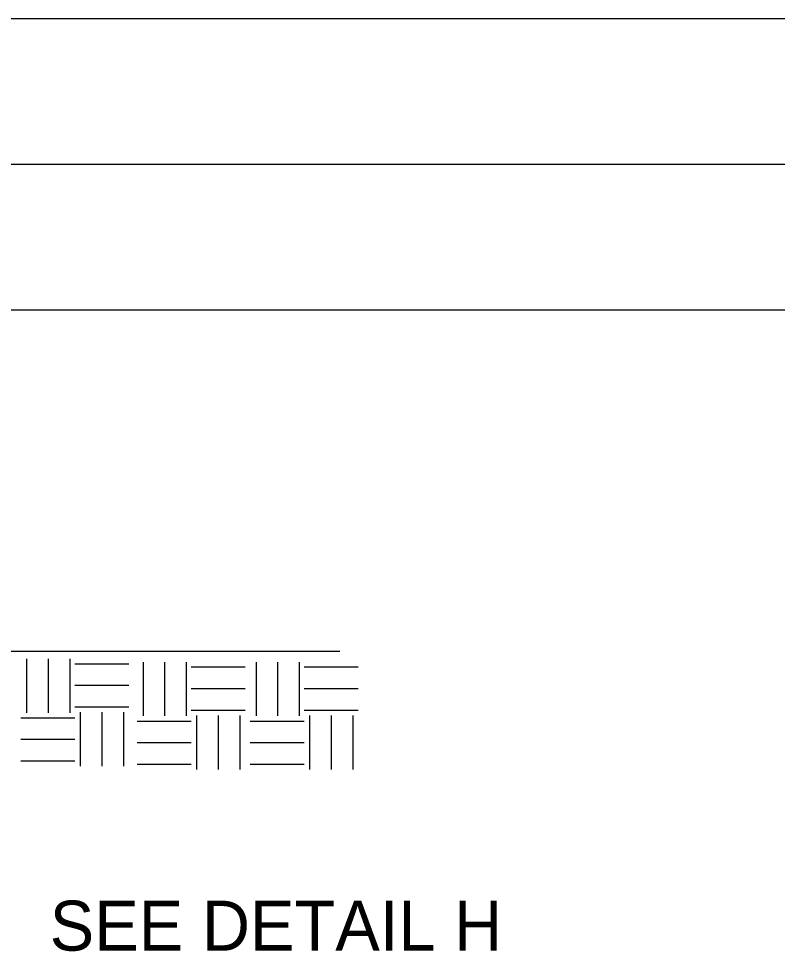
# Model space of a CAD drawing. Extents: x 49991.4 to 50021, y 49987.6 to 50011.4.
# Drawn here: x 50012.221 to 50013.133, y 49996.23 to 49997.35 of the extents above; entities that cross this region are included whole.
import ezdxf

# ---------------------------------------------------------------- set-up
doc = ezdxf.new("R2010")
doc.units = 0
doc.layers.add('Level 1', color=7, linetype='Continuous')
doc.layers.add('Level 2', color=7, linetype='Continuous')

msp = doc.modelspace()

# ---------------------------------------------------------------- linework, layer by layer
at = {"layer": 'Level 1'}
for p, q in [((50009.1825, 49997.3503), (50013.9411, 49997.3503)), ((50009.1825, 49997.1753), (50014.1911, 49997.1753)), ((50009.1825, 49997.0003), (50014.7825, 49997.0003)), ((50012.036, 49996.5902), (50012.6075, 49996.5902)), ((50012.2309, 49996.5813), (50012.2309, 49996.5164)), ((50012.2569, 49996.5813), (50012.2569, 49996.5164)), ((50012.2828, 49996.5813), (50012.2828, 49996.5164)), ((50012.2888, 49996.5753), (50012.3537, 49996.5753)), ((50012.3708, 49996.5773), (50012.3708, 49996.5125)), ((50012.3967, 49996.5773), (50012.3967, 49996.5125)), ((50012.4227, 49996.5773), (50012.4227, 49996.5125)), ((50012.5067, 49996.5773), (50012.5067, 49996.5125)), ((50012.5326, 49996.5773), (50012.5326, 49996.5125)), ((50012.5585, 49996.5773), (50012.5585, 49996.5125)), ((50012.4287, 49996.5713), (50012.4936, 49996.5713)), ((50012.5645, 49996.5713), (50012.6294, 49996.5713)), ((50012.2888, 49996.5493), (50012.3537, 49996.5493)), ((50012.4287, 49996.5454), (50012.4936, 49996.5454)), ((50012.5645, 49996.5454), (50012.6294, 49996.5454)), ((50012.2888, 49996.5234), (50012.3537, 49996.5234)), ((50012.4287, 49996.5194), (50012.4936, 49996.5194)), ((50012.5645, 49996.5194), (50012.6294, 49996.5194)), ((50012.224, 49996.5104), (50012.2888, 49996.5104)), ((50012.2953, 49996.5169), (50012.2953, 49996.452)), ((50012.3213, 49996.5169), (50012.3213, 49996.452)), ((50012.3472, 49996.5169), (50012.3472, 49996.452)), ((50012.4352, 49996.5129), (50012.4352, 49996.4481)), ((50012.4611, 49996.5129), (50012.4611, 49996.4481)), ((50012.4871, 49996.5129), (50012.4871, 49996.4481)), ((50012.571, 49996.5129), (50012.571, 49996.4481)), ((50012.597, 49996.5129), (50012.597, 49996.4481)), ((50012.6229, 49996.5129), (50012.6229, 49996.4481)), ((50012.3638, 49996.5064), (50012.4287, 49996.5064)), ((50012.4997, 49996.5064), (50012.5645, 49996.5064)), ((50012.224, 49996.4845), (50012.2888, 49996.4845)), ((50012.3638, 49996.4805), (50012.4287, 49996.4805)), ((50012.4997, 49996.4805), (50012.5645, 49996.4805)), ((50012.224, 49996.4585), (50012.2888, 49996.4585)), ((50012.3638, 49996.4546), (50012.4287, 49996.4546)), ((50012.4997, 49996.4546), (50012.5645, 49996.4546))]:
    msp.add_line(p, q, dxfattribs=at)

# ---------------------------------------------------------------- texts
at = {"layer": 'Level 2'}
msp.add_text('SEE DETAIL H ', height=0.06, dxfattribs=at).set_placement((50012.2586, 49996.2305))

doc.saveas('drawing.dxf')
